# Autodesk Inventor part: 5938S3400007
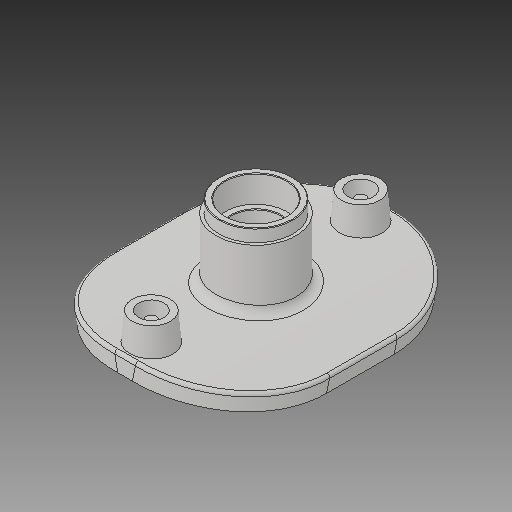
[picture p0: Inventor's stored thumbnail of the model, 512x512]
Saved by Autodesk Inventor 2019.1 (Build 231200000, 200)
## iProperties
Created: 2017-08
Part Number: 5938S3400007
Material: Generic
Description: PLASSON SENSOR ADAPTOR WITH STAINLESS STEEL THREAD 4''16''IPSx3/4''
Document SubType Name: Modeling
Designer: Кирилл
Density: 1 g/cm^3
Appearance: Default
Author: Кирилл
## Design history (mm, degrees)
derived "5938S.ipt"
feature "Solid1::5938S.ipt"
feature "Solid2::5938S.ipt"
feature "Solid3::5938S.ipt"
tag "TaggingFeature1"
body "Solid1"
other parameters: "d0" = 404.6, "d1" = 84.836, "d3" = 102.87, "d4" = 0, "d5" = 38.1762, "d11" = 262.99, "d38" = 1.2138, "d40" = 219.826, "d41" = 15, "d42" = 41.148, "d46" = 5 deg, "d47" = 4, "d51" = 14, "d52" = 0, "d53" = 3, "d54" = 0, "d75" = 0, "d77" = 0, "d78" = 0.24117, "d82" = 35.052, "d83" = 31.3521, "d84" = 28.9404, "d85" = 19.2936, "d86" = 24.117, "d89" = 10.5156, "d90" = 4.90728, "d95" = 3.175, "d97" = 360 deg, "d99" = 7.0104, "d_" = 404.6, "B_" = 84.836, "H_" = 35.052, "L_" = 102.87, "G_" = 24.117
